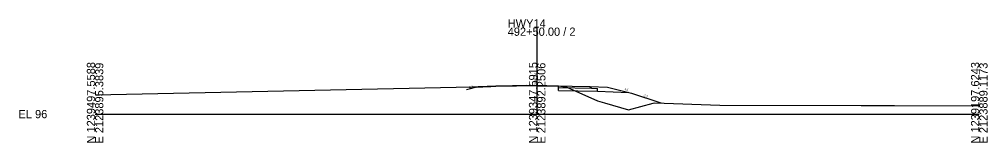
# Model space of a CAD drawing. Extents: x -26 to 303, y -10 to 11521.
# Drawn here: x -25.7 to 302.8, y 3990.3 to 4032.2 of the extents above; entities that cross this region are included whole.
import ezdxf

# ---------------------------------------------------------------- set-up
doc = ezdxf.new("R2010")
doc.units = 0
for name, color, linetype in [('XS_CELL', 7, 'Continuous'), ('XS_P_FINISHED_GRADE', 7, 'Continuous'), ('XS_P_SUBGRADE_GRANULAR', 7, 'Continuous'), ('XS_P_SUBGRADE_LEVELING', 7, 'Continuous'), ('XS_P_SUBGRADE_PAVEMENT', 7, 'Continuous'), ('XS_P_TX_FS_BS', 7, 'Continuous'), ('XS_X_GROUND', 7, 'Continuous'), ('XS_X_GROUND_TX', 7, 'Continuous')]:
    doc.layers.add(name, color=color, linetype=linetype)

msp = doc.modelspace()

# ---------------------------------------------------------------- linework, layer by layer
at = {"layer": 'XS_CELL'}
for p, q in [((150, 4000), (150, 4029.4)), ((0, 4000), (150, 4000)), ((150, 4000), (300, 4000))]:
    msp.add_line(p, q, dxfattribs=at)
at = {"layer": 'XS_P_FINISHED_GRADE'}
for p, q in [((130, 4009.22), (126, 4008.22)), ((136, 4009.46), (130, 4009.22)), ((150, 4009.74), (136, 4009.46)), ((150, 4009.74), (167.86, 4009.38)), ((167.86, 4009.38), (173.86, 4009.14)), ((173.86, 4009.14), (182, 4007.11)), ((182, 4007.11), (191.95, 4003.79))]:
    msp.add_line(p, q, dxfattribs=at)
at = {"layer": 'XS_P_SUBGRADE_GRANULAR'}
for p, q in [((136, 4009.33), (129.4, 4009.07)), ((157.27, 4008.01), (157.27, 4009.01)), ((168.48, 4008.79), (170.48, 4008.71)), ((170.48, 4007.75), (170.48, 4008.71)), ((157.27, 4008.01), (170.48, 4007.75)), ((170.48, 4007.75), (181.15, 4007.32))]:
    msp.add_line(p, q, dxfattribs=at)
at = {"layer": 'XS_P_SUBGRADE_LEVELING'}
for p, q in [((150, 4009.61), (136, 4009.33)), ((136, 4009.33), (136, 4009.46)), ((150, 4009.61), (157.27, 4009.47))]:
    msp.add_line(p, q, dxfattribs=at)
at = {"layer": 'XS_P_SUBGRADE_PAVEMENT'}
for p, q in [((157.27, 4009.01), (157.27, 4009.59)), ((157.27, 4009.01), (168.48, 4008.79)), ((167.86, 4009.38), (168.34, 4009.03)), ((168.34, 4009.03), (168.48, 4008.79))]:
    msp.add_line(p, q, dxfattribs=at)
at = {"layer": 'XS_X_GROUND'}
for p, q in [((0, 4006.52), (133.16, 4009.36)), ((133.16, 4009.36), (134.33, 4009.44)), ((134.33, 4009.44), (135.58, 4009.53)), ((135.58, 4009.53), (141.58, 4009.69)), ((141.58, 4009.69), (146.52, 4009.8)), ((146.52, 4009.8), (150, 4009.74)), ((150, 4009.74), (153.29, 4009.68)), ((153.29, 4009.68), (157.27, 4009.61)), ((157.27, 4009.61), (158.07, 4009.48)), ((158.07, 4009.48), (160.07, 4009.2)), ((160.07, 4009.2), (170.43, 4004.56)), ((170.43, 4004.56), (172.85, 4003.84)), ((172.85, 4003.84), (180.98, 4001.42)), ((180.98, 4001.42), (189.35, 4003.7)), ((189.35, 4003.7), (189.96, 4003.86)), ((189.96, 4003.86), (212.03, 4003.05)), ((212.03, 4003.05), (259.96, 4002.98)), ((259.96, 4002.98), (266.23, 4002.96)), ((266.23, 4002.96), (271.21, 4002.94)), ((271.21, 4002.94), (300, 4002.78))]:
    msp.add_line(p, q, dxfattribs=at)

# ---------------------------------------------------------------- texts
at = {"layer": 'XS_CELL'}
for s, p in [('HWY14', (140, 4029.4)), ('492+50.00 / 2', (140, 4026.6)), ('EL 96', (-26, 3998.6))]:
    msp.add_text(s, height=2.8, dxfattribs=at).set_placement(p)
for s, p in [('N 1239497.5588', (0, 3990)), ('E 2123895.3839', (2.8, 3990)), ('N 1239347.5915', (150, 3990)), ('E 2123892.2506', (152.8, 3990)), ('N 1239197.6243', (300, 3990)), ('E 2123889.1173', (302.8, 3990))]:
    msp.add_text(s, height=2.8, rotation=90, dxfattribs=at).set_placement(p)
at = {"layer": 'XS_P_TX_FS_BS'}
for s, rotation, p in [('4:1', 14.0362, (126.88, 4008.61)), ('4:1', 345.9638, (179.44, 4008.14)), ('3:1', 341.5651, (186.01, 4006.09))]:
    msp.add_text(s, height=0.8, rotation=rotation, dxfattribs=at).set_placement(p)
at = {"layer": 'XS_X_GROUND_TX'}
msp.add_text('105.74', height=1, rotation=90, dxfattribs=at).set_placement((150, 4009.84))

doc.saveas('drawing.dxf')
